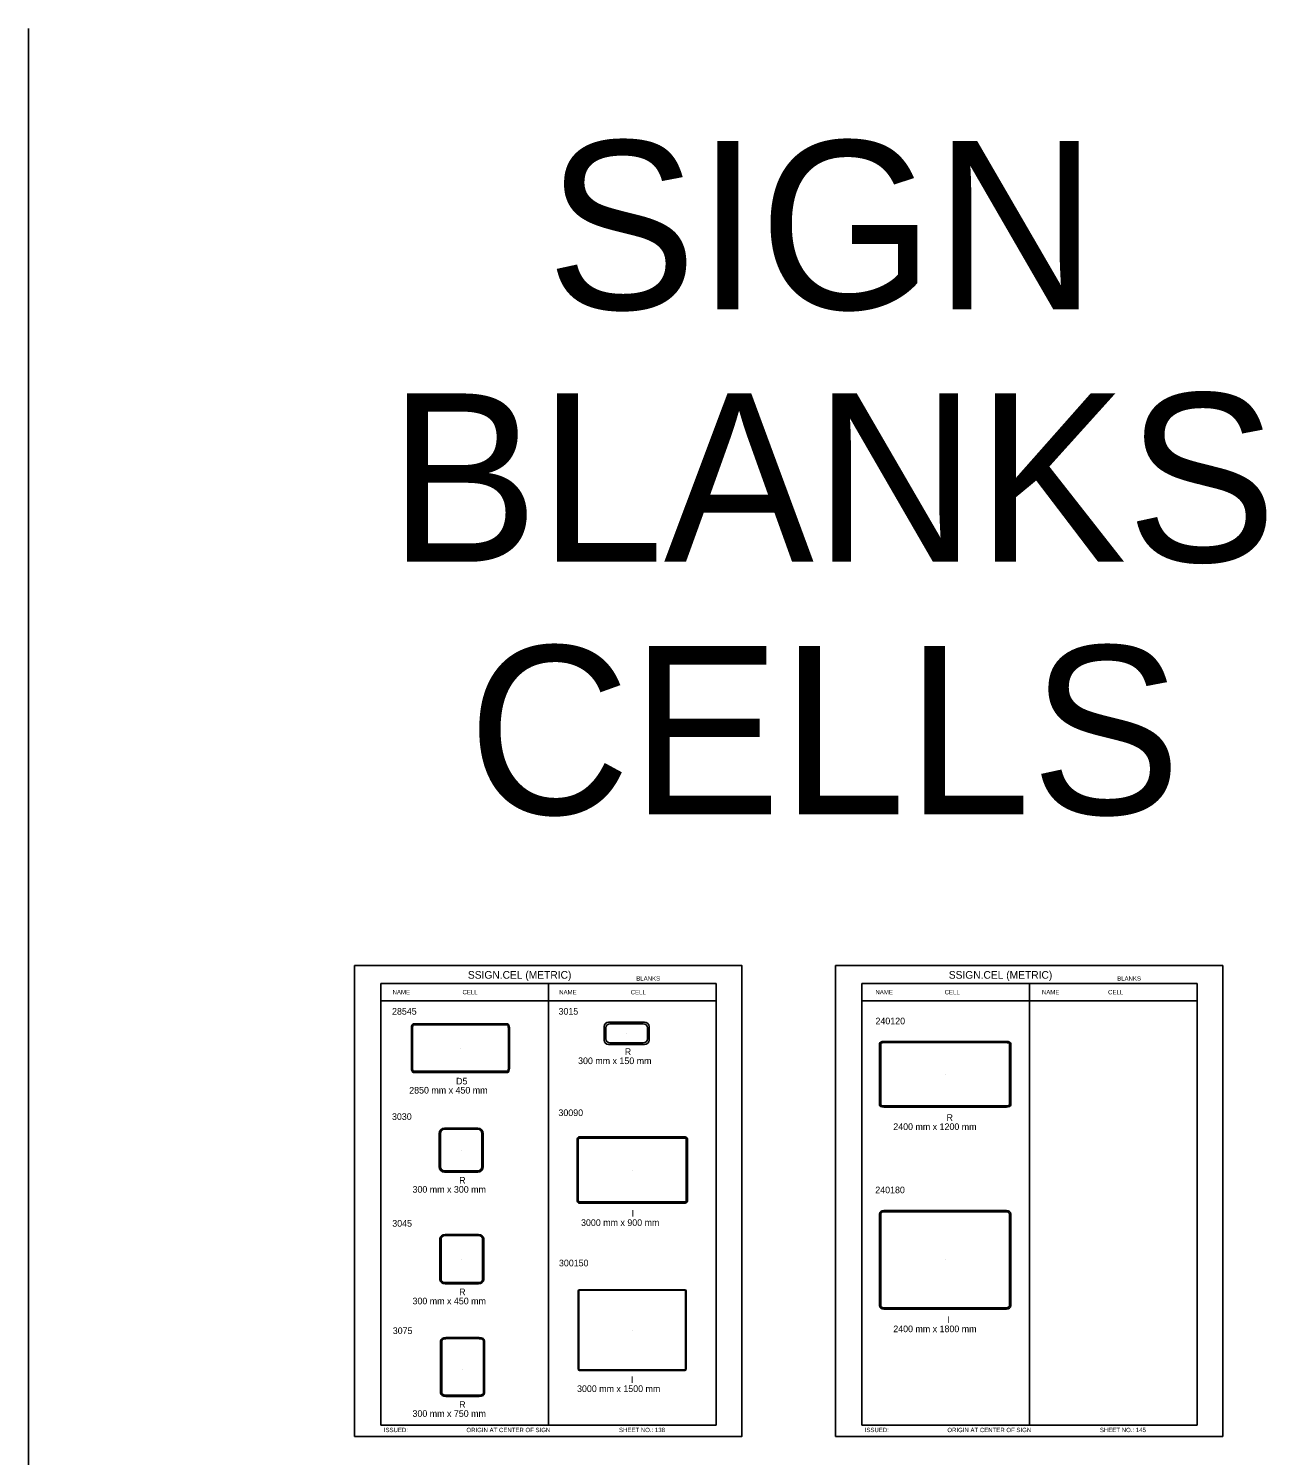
# Model space of a CAD drawing. Extents: x -12 to 6962, y -3756 to 679.
# Drawn here: x 1258 to 1819, y -2328 to -1682 of the extents above; entities that cross this region are included whole.
import ezdxf

# ---------------------------------------------------------------- set-up
doc = ezdxf.new("R2010")
doc.units = 0
for name, color, linetype in [('Level 1', 7, 'Continuous'), ('Level 2', 7, 'Continuous'), ('Level 3', 7, 'Continuous'), ('Level 60', 7, 'Continuous')]:
    doc.layers.add(name, color=color, linetype=linetype)

msp = doc.modelspace()

# ---------------------------------------------------------------- linework, layer by layer
at = {"layer": 'Level 1'}
for p, q in [((1569.58, -2114.07), (1417.83, -2114.07)), ((1417.83, -2114.07), (1417.83, -2314.07)), ((1493.71, -2114.07), (1493.71, -2314.07)), ((1569.58, -2114.07), (1569.58, -2314.07)), ((1787.25, -2114.07), (1635.5, -2114.07)), ((1635.5, -2114.07), (1635.5, -2314.07)), ((1711.37, -2114.07), (1711.37, -2314.07)), ((1787.25, -2114.07), (1787.25, -2314.07)), ((1569.58, -2121.99), (1417.83, -2121.99)), ((1787.25, -2121.99), (1635.5, -2121.99)), ((1518.88, -2139.73), (1518.88, -2133.64)), ((1519.63, -2139.13), (1519.63, -2134.24)), ((1520.91, -2131.61), (1537.17, -2131.61)), ((1521.51, -2132.36), (1536.56, -2132.36)), ((1529.04, -2136.69), (1529.04, -2136.69)), ((1538.44, -2134.24), (1538.44, -2139.13)), ((1539.2, -2133.64), (1539.2, -2139.73)), ((1453.85, -2143.35), (1453.85, -2143.35)), ((1537.17, -2141.77), (1520.91, -2141.77)), ((1536.56, -2141.01), (1521.51, -2141.01)), ((1673.21, -2155.2), (1673.21, -2155.2)), ((1454.17, -2189.53), (1454.17, -2189.53)), ((1531.62, -2198.55), (1531.62, -2198.55)), ((1454.49, -2238.88), (1454.49, -2238.88)), ((1673.21, -2239.19), (1673.21, -2239.19)), ((1507.18, -2288.55), (1507.18, -2253.44)), ((1507.36, -2288.33), (1507.36, -2253.65)), ((1507.67, -2252.71), (1555.46, -2252.71)), ((1507.81, -2252.98), (1555.32, -2252.98)), ((1555.77, -2253.65), (1555.77, -2288.33)), ((1555.95, -2253.44), (1555.95, -2288.55)), ((1531.56, -2270.99), (1531.56, -2270.99)), ((1454.81, -2288.75), (1454.81, -2288.75)), ((1555.46, -2289.28), (1507.67, -2289.28)), ((1555.32, -2289.01), (1507.81, -2289.01)), ((1417.83, -2314.07), (1569.58, -2314.07)), ((1635.5, -2314.07), (1787.25, -2314.07))]:
    msp.add_line(p, q, dxfattribs=at)
for centre, radius, start, end in [((1520.91, -2133.64), 2.03, 90, 180), ((1521.51, -2134.24), 1.88, 90, 180), ((1536.56, -2134.24), 1.88, 0, 90), ((1537.17, -2133.64), 2.03, 0, 90), ((1520.91, -2139.73), 2.03, 180, 270), ((1521.51, -2139.13), 1.88, 180, 270), ((1536.56, -2139.13), 1.88, 270, 0), ((1537.17, -2139.73), 2.03, 270, 0)]:
    msp.add_arc(centre, radius, start, end, dxfattribs=at)
for centre, major_axis, start_param, end_param in [((1507.67, -2253.44), (0, -0.731), 3.141593, 4.712389), ((1507.81, -2253.65), (0, -0.677), 3.141593, 4.712389), ((1555.32, -2253.65), (0, 0.677), 4.712389, 6.283185), ((1555.46, -2253.44), (0, 0.731), 4.712389, 6.283185), ((1507.67, -2288.55), (0, -0.731), 4.712389, 6.283185), ((1507.81, -2288.33), (0, -0.677), 4.712389, 6.283185), ((1555.32, -2288.33), (0, 0.677), 3.141593, 4.712389), ((1555.46, -2288.55), (0, 0.731), 3.141593, 4.712389)]:
    msp.add_ellipse(centre, major_axis=major_axis, ratio=0.666667, start_param=start_param, end_param=end_param, dxfattribs=at)
at = {"layer": 'Level 3'}
for p, q in [((1258.34, -1681.9), (1258.34, -3756.26)), ((1431.65, -2134.25), (1431.65, -2152.45)), ((1432.18, -2134.25), (1432.18, -2152.45)), ((1475.09, -2132.35), (1432.6, -2132.35)), ((1475.09, -2132.89), (1432.6, -2132.89)), ((1475.52, -2152.45), (1475.52, -2134.25)), ((1476.04, -2152.45), (1476.04, -2134.25)), ((1643.5, -2169.07), (1643.5, -2141.33)), ((1644.05, -2169.07), (1644.05, -2141.33)), ((1645.46, -2140.34), (1700.95, -2140.34)), ((1645.46, -2140.9), (1700.95, -2140.9)), ((1702.36, -2141.33), (1702.36, -2169.07)), ((1702.91, -2141.33), (1702.91, -2169.07)), ((1432.6, -2153.8), (1475.09, -2153.8)), ((1432.6, -2154.35), (1475.09, -2154.35)), ((1700.95, -2169.5), (1645.46, -2169.5)), ((1700.95, -2170.05), (1645.46, -2170.05)), ((1444.21, -2182.01), (1444.21, -2197.06)), ((1444.76, -2182.01), (1444.76, -2197.06)), ((1461.69, -2179.57), (1446.64, -2179.57)), ((1461.69, -2180.13), (1446.64, -2180.13)), ((1463.57, -2197.06), (1463.57, -2182.01)), ((1464.13, -2197.06), (1464.13, -2182.01)), ((1506.62, -2185.04), (1506.62, -2212.07)), ((1507.18, -2185.04), (1507.18, -2212.07)), ((1555.61, -2183.55), (1507.64, -2183.55)), ((1555.61, -2184.13), (1507.64, -2184.13)), ((1556.06, -2212.07), (1556.06, -2185.04)), ((1556.62, -2212.07), (1556.62, -2185.04)), ((1446.64, -2198.94), (1461.69, -2198.94)), ((1446.64, -2199.49), (1461.69, -2199.49)), ((1507.64, -2212.98), (1555.61, -2212.98)), ((1507.64, -2213.55), (1555.61, -2213.55)), ((1643.5, -2260), (1643.5, -2218.39)), ((1644.05, -2260), (1644.05, -2218.39)), ((1645.46, -2216.91), (1700.95, -2216.91)), ((1645.46, -2217.46), (1700.95, -2217.46)), ((1702.36, -2218.39), (1702.36, -2260)), ((1702.91, -2218.39), (1702.91, -2260)), ((1462.01, -2227.71), (1446.97, -2227.71)), ((1444.54, -2229.64), (1444.54, -2248.13)), ((1445.09, -2229.64), (1445.09, -2248.13)), ((1462.01, -2228.26), (1446.97, -2228.26)), ((1463.89, -2248.13), (1463.89, -2229.64)), ((1464.44, -2248.13), (1464.44, -2229.64)), ((1446.97, -2249.5), (1462.01, -2249.5)), ((1446.97, -2250.06), (1462.01, -2250.06)), ((1700.95, -2260.92), (1645.46, -2260.92)), ((1700.95, -2261.47), (1645.46, -2261.47)), ((1444.85, -2275.86), (1444.85, -2299.53)), ((1445.41, -2275.86), (1445.41, -2299.53)), ((1462.34, -2274.33), (1447.29, -2274.33)), ((1462.34, -2274.88), (1447.29, -2274.88)), ((1464.22, -2299.53), (1464.22, -2275.86)), ((1464.77, -2299.53), (1464.77, -2275.86)), ((1447.29, -2300.51), (1462.34, -2300.51)), ((1447.29, -2301.06), (1462.34, -2301.06))]:
    msp.add_line(p, q, dxfattribs=at)
for centre, radius, start, end in [((1446.64, -2182.01), 2.43, 90, 180), ((1446.64, -2182.01), 1.88, 90, 180), ((1461.69, -2182.01), 2.43, 0, 90), ((1461.69, -2182.01), 1.88, 0, 90), ((1446.64, -2197.06), 2.43, 180, 270), ((1446.64, -2197.06), 1.88, 180, 270), ((1461.69, -2197.06), 1.88, 270, 0), ((1461.69, -2197.06), 2.43, 270, 0)]:
    msp.add_arc(centre, radius, start, end, dxfattribs=at)
for centre, major_axis, ratio, start_param, end_param in [((1432.6, -2134.25), (0, -1.9), 0.498217, 3.141593, 4.712389), ((1432.6, -2134.25), (0, -1.36), 0.313523, 3.141593, 4.712389), ((1475.09, -2134.25), (0, 1.9), 0.498217, 4.712389, 6.283185), ((1475.09, -2134.25), (0, 1.36), 0.313523, 4.712389, 6.283185), ((1645.46, -2141.33), (-1.97, 0), 0.5, 4.712389, 6.283185), ((1645.46, -2141.33), (-1.41, 0), 0.30451, 4.712389, 6.283185), ((1700.95, -2141.33), (-1.97, 0), 0.5, 3.141593, 4.712389), ((1700.95, -2141.33), (-1.41, 0), 0.30451, 3.141593, 4.712389), ((1432.6, -2152.45), (0, -1.9), 0.498217, 4.712389, 6.283185), ((1432.6, -2152.45), (0, -1.36), 0.313523, 4.712389, 6.283185), ((1475.09, -2152.45), (0, 1.36), 0.313523, 3.141593, 4.712389), ((1475.09, -2152.45), (0, 1.9), 0.498217, 3.141593, 4.712389), ((1645.46, -2169.07), (1.97, 0), 0.5, 3.141593, 4.712389), ((1645.46, -2169.07), (1.41, 0), 0.30451, 3.141593, 4.712389), ((1700.95, -2169.07), (1.97, 0), 0.5, 4.712389, 6.283185), ((1700.95, -2169.07), (1.41, 0), 0.30451, 4.712389, 6.283185), ((1507.64, -2185.04), (0, -1.49), 0.681945, 3.141593, 4.712389), ((1507.64, -2185.04), (0, -0.912), 0.49945, 3.141593, 4.712389), ((1555.61, -2185.04), (0, 1.49), 0.681945, 4.712389, 6.283185), ((1555.61, -2185.04), (0, 0.912), 0.49945, 4.712389, 6.283185), ((1507.64, -2212.07), (0, -1.49), 0.681945, 4.712389, 6.283185), ((1507.64, -2212.07), (0, -0.912), 0.49945, 4.712389, 6.283185), ((1555.61, -2212.07), (0, 0.912), 0.49945, 3.141593, 4.712389), ((1555.61, -2212.07), (0, 1.49), 0.681945, 3.141593, 4.712389), ((1645.46, -2218.39), (-1.97, 0), 0.75, 4.712389, 6.283185), ((1645.46, -2218.39), (-1.41, 0), 0.652255, 4.712389, 6.283185), ((1700.95, -2218.39), (-1.97, 0), 0.75, 3.141593, 4.712389), ((1700.95, -2218.39), (-1.41, 0), 0.652255, 3.141593, 4.712389), ((1446.97, -2229.64), (-2.43, 0), 0.79424, 4.712389, 6.283185), ((1462.01, -2229.64), (-2.43, 0), 0.79424, 3.141593, 4.712389), ((1446.97, -2229.64), (-1.88, 0), 0.7337, 4.712389, 6.283185), ((1462.01, -2229.64), (-1.88, 0), 0.7337, 3.141593, 4.712389), ((1446.97, -2248.13), (2.43, 0), 0.79424, 3.141593, 4.712389), ((1446.97, -2248.13), (1.88, 0), 0.7337, 3.141593, 4.712389), ((1462.01, -2248.13), (1.88, 0), 0.7337, 4.712389, 6.283185), ((1462.01, -2248.13), (2.43, 0), 0.79424, 4.712389, 6.283185), ((1645.46, -2260), (1.97, 0), 0.75, 3.141593, 4.712389), ((1645.46, -2260), (1.41, 0), 0.652255, 3.141593, 4.712389), ((1700.95, -2260), (1.97, 0), 0.75, 4.712389, 6.283185), ((1700.95, -2260), (1.41, 0), 0.652255, 4.712389, 6.283185), ((1447.29, -2275.86), (-2.43, 0), 0.629122, 4.712389, 6.283185), ((1447.29, -2275.86), (-1.88, 0), 0.52, 4.712389, 6.283185), ((1462.34, -2275.86), (-2.43, 0), 0.629122, 3.141593, 4.712389), ((1462.34, -2275.86), (-1.88, 0), 0.52, 3.141593, 4.712389), ((1447.29, -2299.53), (2.43, 0), 0.629122, 3.141593, 4.712389), ((1447.29, -2299.53), (1.88, 0), 0.52, 3.141593, 4.712389), ((1462.34, -2299.53), (1.88, 0), 0.52, 4.712389, 6.283185), ((1462.34, -2299.53), (2.43, 0), 0.629122, 4.712389, 6.283185)]:
    msp.add_ellipse(centre, major_axis=major_axis, ratio=ratio, start_param=start_param, end_param=end_param, dxfattribs=at)
at = {"layer": 'Level 60'}
for points in [[(1405.95, -2319.12), (1581.21, -2319.12), (1581.21, -2106.02), (1405.95, -2106.02)], [(1623.62, -2319.12), (1798.88, -2319.12), (1798.88, -2106.02), (1623.62, -2106.02)]]:
    msp.add_lwpolyline(points, close=True, dxfattribs=at)

# ---------------------------------------------------------------- texts
at = {"layer": 'Level 2'}
for s, p in [('28545', (1422.87, -2128.23)), ('3015', (1498.22, -2128.23)), ('240120', (1641.7, -2132.59)), ('3030', (1422.85, -2175.86)), ('30090', (1498.19, -2174.13)), ('240180', (1641.61, -2209.05)), ('3045', (1422.98, -2224.2)), ('300150', (1498.42, -2242.15)), ('3075', (1423.21, -2272.78))]:
    msp.add_text(s, height=3, dxfattribs=at).set_placement(p)
at = {"layer": 'Level 3'}
for s, height, p in [('SIGN', 76.194, (1492.8, -1808.96)), ('BLANKS', 76.194, (1421.26, -1923.25)), ('CELLS', 76.194, (1457.17, -2037.54)), ('SSIGN.CEL (METRIC)', 3.4642, (1457.21, -2111.96)), ('BLANKS', 1.979, (1533.42, -2112.83)), ('SSIGN.CEL (METRIC)', 3.4642, (1674.88, -2111.96)), ('BLANKS', 1.979, (1751.09, -2112.83)), ('NAME', 1.98, (1423.13, -2119.03)), ('CELL', 1.98, (1454.77, -2119.03)), ('NAME', 1.98, (1498.53, -2119.03)), ('CELL', 1.98, (1530.9, -2119.03)), ('NAME', 1.98, (1641.68, -2119.03)), ('CELL', 1.98, (1673, -2119.03)), ('NAME', 1.98, (1717.04, -2119.03)), ('CELL', 1.98, (1746.98, -2119.03)), ('R', 3, (1528.22, -2146.49)), ('300 mm x 150 mm', 3, (1507.09, -2150.61)), ('D5', 3, (1451.87, -2159.82)), ('2850 mm x 450 mm', 3, (1430.65, -2163.94)), ('R', 3, (1673.86, -2176.31)), ('2400 mm x 1200 mm', 3, (1649.75, -2180.43)), ('R', 3, (1453.27, -2204.69)), ('300 mm x 300 mm', 3, (1432.14, -2208.81)), ('3000 mm x 900 mm', 3, (1508.42, -2223.85)), ('I', 3, (1531.3, -2219.72)), ('R', 3, (1453.27, -2255.22)), ('300 mm x 450 mm', 3, (1432.14, -2259.34)), ('I', 3, (1674.11, -2267.83)), ('2400 mm x 1800 mm', 3, (1649.75, -2271.95)), ('I', 3, (1530.97, -2294.91)), ('3000 mm x 1500 mm', 3, (1506.61, -2299.03)), ('R', 3, (1453.27, -2306.17)), ('300 mm x 750 mm', 3, (1432.14, -2310.29)), ('ISSUED:', 1.98, (1419.17, -2317.19)), ('ORIGIN AT CENTER OF SIGN', 1.9795, (1456.55, -2317.19)), ('SHEET NO.: 138', 1.9795, (1525.61, -2317.18)), ('ISSUED:', 1.98, (1636.84, -2317.19)), ('ORIGIN AT CENTER OF SIGN', 1.9795, (1674.22, -2317.19)), ('SHEET NO.: 145', 1.9795, (1743.28, -2317.19))]:
    msp.add_text(s, height=height, dxfattribs=at).set_placement(p)

doc.saveas('drawing.dxf')
